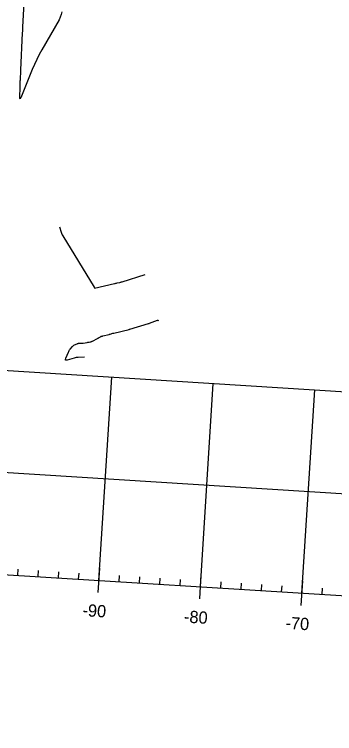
# Model space of a CAD drawing. Extents: x 658976 to 668721, y 639543 to 647196.
# Drawn here: x 659920 to 660077.5, y 642017.6 to 642370.7 of the extents above; entities that cross this region are included whole.
import ezdxf

# ---------------------------------------------------------------- set-up
doc = ezdxf.new("R2010")
doc.units = 0
for name, color, linetype in [('Ex_Minor Contours', 7, 'Continuous'), ('R_Axis', 7, 'Continuous'), ('R_Axis Annot', 7, 'Continuous'), ('R_Grid', 7, 'Continuous')]:
    doc.layers.add(name, color=color, linetype=linetype)

msp = doc.modelspace()

# ---------------------------------------------------------------- linework, layer by layer
at = {"layer": 'Ex_Minor Contours'}
for points in [[(659943.33, 642371.87), (659943.05, 642370.55), (659942.61, 642369.27), (659942, 642368.04), (659933.57, 642353.33), (659932.27, 642350.97), (659931.05, 642348.57), (659929.91, 642346.14), (659928.85, 642343.66), (659923.16, 642329.76), (659922.97, 642329.36), (659922.83, 642329.24), (659922.76, 642329.41), (659922.75, 642329.85), (659922.81, 642332.17), (659922.82, 642332.75), (659922.84, 642333.33), (659922.85, 642333.91), (659922.87, 642334.49), (659922.95, 642337.55), (659922.96, 642338.03), (659922.98, 642338.51), (659923, 642339), (659923.02, 642339.48), (659923.16, 642342.18), (659923.18, 642342.57), (659923.2, 642342.97), (659923.21, 642343.06), (659923.21, 642343.16), (659923.22, 642343.26), (659923.22, 642343.36), (659924.11, 642361.69), (659924.15, 642362.41), (659924.19, 642363.14), (659924.22, 642363.86), (659924.26, 642364.59), (659925.14, 642382.09)], [(659942.23, 642266.39), (659943.08, 642263.73), (659943.24, 642263.3), (659943.42, 642262.87), (659943.62, 642262.46), (659943.85, 642262.05), (659959.29, 642236.72), (659959.31, 642236.68), (659959.33, 642236.64), (659959.35, 642236.59), (659959.36, 642236.55), (659959.43, 642236.29), (659959.43, 642236.29), (659959.44, 642236.28), (659959.44, 642236.28), (659959.45, 642236.28), (659959.47, 642236.28), (659959.48, 642236.28), (659959.49, 642236.29), (659959.49, 642236.29), (659959.5, 642236.29), (659969.34, 642238.56), (659969.65, 642238.63), (659969.96, 642238.7), (659970.28, 642238.77), (659970.59, 642238.84), (659971.84, 642239.11), (659972.15, 642239.19), (659972.46, 642239.27), (659972.77, 642239.35), (659973.07, 642239.45), (659984.34, 642243.06)], [(659954.47, 642202.41), (659951.47, 642202.29), (659950.97, 642202.26), (659950.48, 642202.19), (659949.99, 642202.1), (659949.51, 642201.97), (659946.07, 642200.97), (659945.52, 642200.88), (659945.21, 642201), (659945.13, 642201.32), (659945.28, 642201.85), (659946.58, 642204.91), (659946.75, 642205.27), (659946.95, 642205.62), (659947.17, 642205.95), (659947.42, 642206.27), (659948.58, 642207.62), (659948.8, 642207.85), (659949.05, 642208.06), (659949.31, 642208.24), (659949.59, 642208.39), (659950.9, 642209.03), (659951.12, 642209.13), (659951.35, 642209.19), (659951.59, 642209.24), (659951.83, 642209.25), (659952.82, 642209.27), (659953.06, 642209.28), (659953.31, 642209.29), (659953.55, 642209.32), (659953.8, 642209.35), (659955.87, 642209.69), (659956.09, 642209.72), (659956.31, 642209.76), (659956.53, 642209.8), (659956.76, 642209.85), (659957.65, 642210.02), (659957.87, 642210.07), (659958.08, 642210.13), (659958.29, 642210.22), (659958.49, 642210.31), (659960.9, 642211.59), (659960.97, 642211.62), (659961.03, 642211.66), (659961.1, 642211.69), (659961.17, 642211.73), (659961.43, 642211.88), (659961.5, 642211.91), (659961.56, 642211.95), (659961.63, 642211.99), (659961.7, 642212.02), (659962.72, 642212.53), (659962.75, 642212.55), (659962.75, 642212.56), (659962.74, 642212.57), (659962.71, 642212.57), (659962.54, 642212.55), (659962.51, 642212.55), (659962.49, 642212.55), (659962.5, 642212.56), (659962.54, 642212.57), (659963.12, 642212.72), (659963.23, 642212.74), (659963.34, 642212.77), (659963.45, 642212.8), (659963.56, 642212.83), (659966.71, 642213.61), (659966.83, 642213.64), (659966.95, 642213.67), (659967.08, 642213.71), (659967.2, 642213.74), (659968.5, 642214.13), (659968.6, 642214.16), (659968.69, 642214.18), (659968.79, 642214.21), (659968.88, 642214.23), (659976.41, 642216.06), (659976.53, 642216.09), (659976.65, 642216.12), (659976.77, 642216.16), (659976.89, 642216.19), (659986.04, 642218.91), (659986.15, 642218.94), (659986.26, 642218.98), (659986.37, 642219.02), (659986.48, 642219.06), (659990.42, 642220.52), (659990.46, 642220.52), (659990.49, 642220.52), (659990.52, 642220.51), (659990.55, 642220.48), (659990.66, 642220.34), (659990.68, 642220.32), (659990.69, 642220.31), (659990.69, 642220.33), (659990.69, 642220.36), (659990.62, 642220.62)]]:
    msp.add_lwpolyline(points, dxfattribs=at)
at = {"layer": 'R_Axis'}
for p, q in [((659662.22, 642111.64), (661159.27, 642017.62)), ((659961.25, 642086.85), (659962, 642098.83)), ((659921.71, 642095.35), (659921.89, 642098.34)), ((659931.69, 642094.72), (659931.87, 642097.71)), ((659941.67, 642094.09), (659941.85, 642097.09)), ((659951.65, 642093.47), (659951.83, 642096.46)), ((659971.61, 642092.21), (659971.8, 642095.21)), ((660011.15, 642083.72), (660011.9, 642095.69)), ((659981.59, 642091.59), (659981.78, 642094.58)), ((659991.57, 642090.96), (659991.76, 642093.95)), ((660001.55, 642090.33), (660001.74, 642093.33)), ((660021.51, 642089.08), (660021.7, 642092.07)), ((660061.05, 642080.58), (660061.81, 642092.56)), ((660031.49, 642088.45), (660031.68, 642091.45)), ((660041.47, 642087.83), (660041.66, 642090.82)), ((660051.45, 642087.2), (660051.64, 642090.19)), ((660071.41, 642085.95), (660071.6, 642088.94))]:
    msp.add_line(p, q, dxfattribs=at)
at = {"layer": 'R_Grid'}
for p, q in [((659668.48, 642211.45), (661165.54, 642117.43)), ((659961.63, 642092.84), (659967.9, 642192.64)), ((660011.53, 642089.71), (660017.8, 642189.51)), ((660061.43, 642086.57), (660067.7, 642186.38)), ((659665.35, 642161.55), (661162.4, 642067.52)), ((659662.22, 642111.64), (661159.27, 642017.62))]:
    msp.add_line(p, q, dxfattribs=at)

# ---------------------------------------------------------------- texts
at = {"layer": 'R_Axis Annot'}
for s, p in [('-90', (659953.4, 642075.32)), ('-80', (660003.31, 642072.19)), ('-70', (660053.21, 642069.05))]:
    msp.add_text(s, height=6, rotation=356.4063, dxfattribs=at).set_placement(p)

doc.saveas('drawing.dxf')
